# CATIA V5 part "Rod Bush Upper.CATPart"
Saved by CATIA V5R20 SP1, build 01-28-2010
Part number: Rod Bush Upper
Bounding box of the stored display mesh (mm): x -12 to 12, y -11.818 to 11.818, z -21 to 21
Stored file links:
  D:\v5_r20\psrt_files_downloaded\c13-catia-v5r20-prt\c13-catia-v5r20-figr-13-41\Part & Asm files\Rod Bush Upper.CATPart
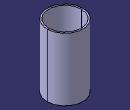
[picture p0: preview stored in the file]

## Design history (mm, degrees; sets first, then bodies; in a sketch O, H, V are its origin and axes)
Body1 (main body)
  Sketch1 on xy-plane, origin (0, 0, 0), H (1, 0, 0), V (0, 1, 0)
    circle A1 centre (0, 0) radius 11
    circle A2 centre (0, 0) radius 12
    point P1 (0, 0)
    radius A2 = 12
    radius A1 = 11
    coincidence: P1 H
    concentricity: A1 A2
  Pad1: profile Sketch1, direction (0, 0, 1), length 21, mirrored extent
